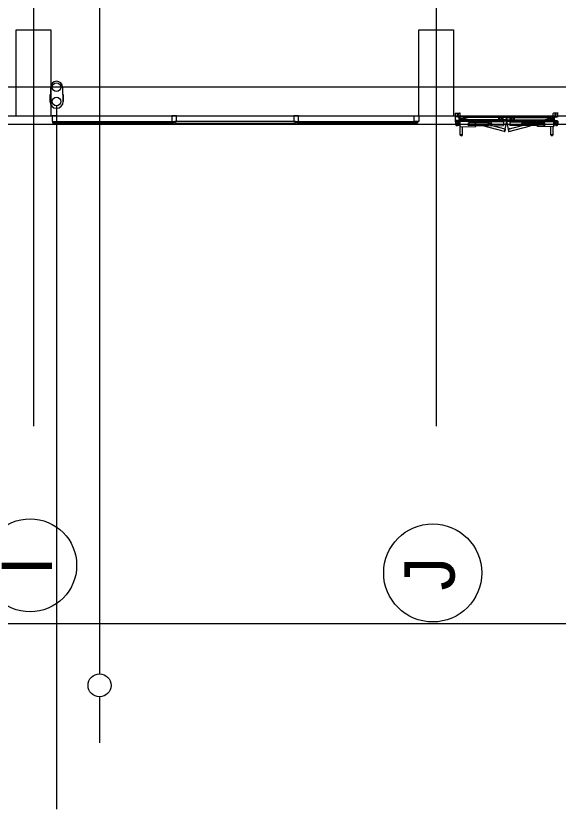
# Model space of a CAD drawing. Extents: x -264205 to -263659, y -1242401 to -1242060.
# Drawn here: x -263862.78 to -263853.35, y -1242253.37 to -1242239.57 of the extents above; entities that cross this region are included whole.
import ezdxf

# ---------------------------------------------------------------- set-up
doc = ezdxf.new("R2010")
doc.units = 0
for name, color, linetype in [('OBRUBNIKY_KOMUNIKACIE_PROJEKT', 7, 'Continuous'), ('OSI_STAVBY_KFA', 7, 'Continuous'), ('SITUACIA_DSP_2D', 7, 'Continuous')]:
    doc.layers.add(name, color=color, linetype=linetype)

msp = doc.modelspace()

# ---------------------------------------------------------------- linework, layer by layer
at = {"layer": 'OBRUBNIKY_KOMUNIKACIE_PROJEKT'}
msp.add_line((-263822.79, -1242241.457), (-263894.968, -1242241.457), dxfattribs=at)
at = {"layer": 'OSI_STAVBY_KFA'}
for p, q in [((-263862.468, -1242083.237), (-263862.468, -1242246.707)), ((-263855.468, -1242083.237), (-263855.468, -1242246.707)), ((-263792.653, -1242240.807), (-263911.523, -1242240.807))]:
    msp.add_line(p, q, dxfattribs=at)
for centre, radius in [((-263862.528, -1242249.126), 0.809), ((-263855.528, -1242249.258), 0.853)]:
    msp.add_circle(centre, radius, dxfattribs=at)
at = {"layer": 'SITUACIA_DSP_2D'}
for p, q in [((-263861.318, -1242235.757), (-263861.321, -1242251.015)), ((-263862.768, -1242241.312), (-263862.768, -1242239.812)), ((-263862.768, -1242239.812), (-263862.168, -1242239.812)), ((-263862.168, -1242239.812), (-263862.168, -1242241.312)), ((-263855.768, -1242241.312), (-263855.768, -1242239.812)), ((-263855.768, -1242239.812), (-263855.168, -1242239.812)), ((-263855.168, -1242239.812), (-263855.168, -1242241.312)), ((-263862.171, -1242240.807), (-263862.171, -1242240.932)), ((-263861.965, -1242240.807), (-263861.965, -1242240.932)), ((-263862.171, -1242240.932), (-263862.185, -1242240.946)), ((-263862.185, -1242240.946), (-263862.185, -1242241.057)), ((-263861.965, -1242240.932), (-263861.951, -1242240.946)), ((-263861.951, -1242240.946), (-263861.951, -1242241.057)), ((-263861.951, -1242241.057), (-263861.951, -1242240.946)), ((-263862.068, -1242241.132), (-263862.068, -1242253.368)), ((-263894.581, -1242241.307), (-263822.79, -1242241.307)), ((-263862.168, -1242241.312), (-263862.768, -1242241.312)), ((-263862.063, -1242241.307), (-263862.143, -1242241.307)), ((-263862.143, -1242241.307), (-263862.143, -1242241.407)), ((-263862.063, -1242241.407), (-263862.063, -1242241.307)), ((-263859.983, -1242241.307), (-263860.063, -1242241.307)), ((-263860.063, -1242241.307), (-263860.063, -1242241.407)), ((-263859.983, -1242241.407), (-263859.983, -1242241.307)), ((-263857.863, -1242241.307), (-263857.943, -1242241.307)), ((-263857.943, -1242241.307), (-263857.943, -1242241.407)), ((-263857.863, -1242241.407), (-263857.863, -1242241.307)), ((-263855.848, -1242241.407), (-263855.848, -1242241.307)), ((-263855.848, -1242241.307), (-263855.768, -1242241.307)), ((-263855.768, -1242241.307), (-263855.768, -1242241.407)), ((-263855.168, -1242241.312), (-263855.768, -1242241.312)), ((-263855.137, -1242241.257), (-263855.061, -1242241.257)), ((-263855.137, -1242241.307), (-263855.137, -1242241.407)), ((-263854.243, -1242241.317), (-263855.137, -1242241.317)), ((-263855.131, -1242241.317), (-263855.131, -1242241.257)), ((-263855.121, -1242241.325), (-263855.121, -1242241.317)), ((-263855.1, -1242241.325), (-263855.121, -1242241.325)), ((-263855.104, -1242241.282), (-263855.078, -1242241.282)), ((-263855.091, -1242241.295), (-263855.091, -1242241.269)), ((-263855.057, -1242241.397), (-263855.057, -1242241.317)), ((-263855.051, -1242241.317), (-263855.051, -1242241.267)), ((-263855.051, -1242241.397), (-263855.051, -1242241.317)), ((-263854.248, -1242241.337), (-263855.006, -1242241.337)), ((-263855.006, -1242241.377), (-263855.006, -1242241.337)), ((-263854.25, -1242241.335), (-263854.28, -1242241.335)), ((-263854.28, -1242241.337), (-263854.28, -1242241.335)), ((-263854.248, -1242241.377), (-263854.248, -1242241.337)), ((-263854.246, -1242241.375), (-263854.246, -1242241.339)), ((-263854.243, -1242241.317), (-263853.348, -1242241.317)), ((-263854.24, -1242241.375), (-263854.24, -1242241.339)), ((-263854.238, -1242241.337), (-263853.479, -1242241.337)), ((-263854.238, -1242241.377), (-263854.238, -1242241.337)), ((-263854.236, -1242241.335), (-263854.206, -1242241.335)), ((-263854.206, -1242241.337), (-263854.206, -1242241.335)), ((-263853.479, -1242241.377), (-263853.479, -1242241.337)), ((-263853.434, -1242241.317), (-263853.434, -1242241.267)), ((-263853.434, -1242241.397), (-263853.434, -1242241.317)), ((-263853.428, -1242241.397), (-263853.428, -1242241.317)), ((-263853.348, -1242241.257), (-263853.424, -1242241.257)), ((-263853.381, -1242241.282), (-263853.407, -1242241.282)), ((-263853.394, -1242241.295), (-263853.394, -1242241.269)), ((-263853.385, -1242241.325), (-263853.364, -1242241.325)), ((-263853.364, -1242241.325), (-263853.364, -1242241.317)), ((-263853.354, -1242241.317), (-263853.354, -1242241.257)), ((-263822.79, -1242241.457), (-263894.968, -1242241.457)), ((-263862.143, -1242241.407), (-263862.103, -1242241.407)), ((-263862.133, -1242241.432), (-263862.133, -1242241.407)), ((-263862.133, -1242241.407), (-263860.033, -1242241.407)), ((-263860.033, -1242241.432), (-263862.133, -1242241.432)), ((-263862.103, -1242241.407), (-263862.063, -1242241.407)), ((-263860.063, -1242241.407), (-263860.023, -1242241.407)), ((-263860.033, -1242241.407), (-263860.033, -1242241.432)), ((-263860.023, -1242241.407), (-263859.983, -1242241.407)), ((-263857.913, -1242241.407), (-263860.013, -1242241.407)), ((-263860.013, -1242241.407), (-263860.013, -1242241.432)), ((-263860.013, -1242241.432), (-263857.913, -1242241.432)), ((-263857.943, -1242241.407), (-263857.853, -1242241.407)), ((-263857.913, -1242241.432), (-263857.913, -1242241.407)), ((-263857.893, -1242241.432), (-263857.893, -1242241.407)), ((-263857.893, -1242241.407), (-263855.793, -1242241.407)), ((-263855.793, -1242241.432), (-263857.893, -1242241.432)), ((-263857.853, -1242241.407), (-263857.863, -1242241.407)), ((-263855.808, -1242241.407), (-263855.848, -1242241.407)), ((-263855.768, -1242241.407), (-263855.808, -1242241.407)), ((-263855.793, -1242241.407), (-263855.793, -1242241.432)), ((-263854.243, -1242241.397), (-263855.137, -1242241.397)), ((-263855.132, -1242241.397), (-263855.132, -1242241.407)), ((-263855.132, -1242241.397), (-263855.062, -1242241.397)), ((-263855.132, -1242241.407), (-263855.132, -1242241.457)), ((-263855.132, -1242241.407), (-263855.062, -1242241.407)), ((-263855.113, -1242241.407), (-263855.13, -1242241.407)), ((-263855.13, -1242241.409), (-263855.13, -1242241.407)), ((-263855.113, -1242241.409), (-263855.13, -1242241.409)), ((-263855.115, -1242241.409), (-263855.128, -1242241.409)), ((-263855.128, -1242241.409), (-263855.128, -1242241.415)), ((-263855.128, -1242241.415), (-263855.115, -1242241.415)), ((-263855.127, -1242241.457), (-263855.096, -1242241.457)), ((-263855.122, -1242241.417), (-263855.122, -1242241.403)), ((-263855.122, -1242241.409), (-263855.122, -1242241.414)), ((-263855.122, -1242241.451), (-263855.112, -1242241.445)), ((-263855.122, -1242241.463), (-263855.122, -1242241.451)), ((-263855.112, -1242241.469), (-263855.122, -1242241.463)), ((-263855.1, -1242241.39), (-263855.121, -1242241.39)), ((-263855.121, -1242241.397), (-263855.121, -1242241.39)), ((-263855.115, -1242241.415), (-263855.115, -1242241.409)), ((-263855.113, -1242241.409), (-263855.113, -1242241.407)), ((-263855.056, -1242241.441), (-263855.112, -1242241.442)), ((-263855.112, -1242241.473), (-263855.112, -1242241.442)), ((-263855.112, -1242241.445), (-263855.101, -1242241.451)), ((-263855.101, -1242241.463), (-263855.112, -1242241.469)), ((-263855.111, -1242241.472), (-263855.055, -1242241.471)), ((-263855.101, -1242241.451), (-263855.101, -1242241.463)), ((-263855.092, -1242241.407), (-263855.092, -1242241.442)), ((-263855.092, -1242241.432), (-263855.081, -1242241.432)), ((-263855.091, -1242241.442), (-263855.091, -1242241.423)), ((-263855.064, -1242241.407), (-263855.081, -1242241.407)), ((-263855.081, -1242241.409), (-263855.081, -1242241.407)), ((-263855.064, -1242241.409), (-263855.081, -1242241.409)), ((-263855.066, -1242241.409), (-263855.079, -1242241.409)), ((-263855.079, -1242241.409), (-263855.079, -1242241.415)), ((-263855.079, -1242241.415), (-263855.066, -1242241.415)), ((-263855.073, -1242241.417), (-263855.073, -1242241.403)), ((-263855.073, -1242241.409), (-263855.073, -1242241.414)), ((-263855.066, -1242241.415), (-263855.066, -1242241.409)), ((-263855.064, -1242241.409), (-263855.064, -1242241.407)), ((-263855.062, -1242241.397), (-263855.062, -1242241.407)), ((-263855.057, -1242241.345), (-263855.057, -1242241.37)), ((-263855.057, -1242241.345), (-263855.047, -1242241.345)), ((-263855.057, -1242241.37), (-263855.047, -1242241.37)), ((-263854.781, -1242241.407), (-263855.056, -1242241.413)), ((-263855.056, -1242241.413), (-263855.055, -1242241.5)), ((-263855.012, -1242241.383), (-263855.052, -1242241.383)), ((-263855.052, -1242241.413), (-263855.052, -1242241.383)), ((-263855.051, -1242241.413), (-263855.051, -1242241.397)), ((-263855.047, -1242241.345), (-263855.047, -1242241.37)), ((-263855.047, -1242241.356), (-263855.037, -1242241.349)), ((-263855.047, -1242241.358), (-263855.047, -1242241.356)), ((-263855.037, -1242241.365), (-263855.047, -1242241.358)), ((-263855.044, -1242241.373), (-263855.019, -1242241.373)), ((-263855.044, -1242241.383), (-263855.044, -1242241.373)), ((-263855.044, -1242241.383), (-263855.019, -1242241.383)), ((-263855.04, -1242241.363), (-263855.033, -1242241.373)), ((-263855.033, -1242241.373), (-263855.031, -1242241.373)), ((-263855.031, -1242241.373), (-263855.023, -1242241.363)), ((-263855.028, -1242241.367), (-263855.017, -1242241.362)), ((-263855.026, -1242241.349), (-263855.016, -1242241.356)), ((-263855.016, -1242241.358), (-263855.026, -1242241.365)), ((-263855.016, -1242241.36), (-263855.024, -1242241.351)), ((-263855.02, -1242241.373), (-263855.013, -1242241.349)), ((-263855.01, -1242241.376), (-263855.02, -1242241.373)), ((-263855.019, -1242241.383), (-263855.019, -1242241.373)), ((-263855.017, -1242241.362), (-263855.016, -1242241.36)), ((-263855.006, -1242241.345), (-263855.016, -1242241.345)), ((-263855.016, -1242241.345), (-263855.016, -1242241.37)), ((-263855.016, -1242241.356), (-263855.016, -1242241.358)), ((-263855.006, -1242241.37), (-263855.016, -1242241.37)), ((-263855.004, -1242241.352), (-263855.013, -1242241.349)), ((-263855.002, -1242241.345), (-263855.012, -1242241.383)), ((-263855.012, -1242241.412), (-263855.012, -1242241.383)), ((-263854.96, -1242241.397), (-263855.012, -1242241.383)), ((-263855.006, -1242241.345), (-263855.006, -1242241.37)), ((-263854.248, -1242241.377), (-263855.006, -1242241.377)), ((-263854.805, -1242241.397), (-263855.002, -1242241.345)), ((-263854.781, -1242241.426), (-263854.907, -1242241.428)), ((-263854.906, -1242241.478), (-263854.907, -1242241.428)), ((-263854.78, -1242241.476), (-263854.906, -1242241.478)), ((-263854.896, -1242241.478), (-263854.897, -1242241.428)), ((-263854.79, -1242241.476), (-263854.791, -1242241.426)), ((-263854.78, -1242241.494), (-263854.781, -1242241.407)), ((-263854.3, -1242241.411), (-263854.781, -1242241.42)), ((-263854.558, -1242241.426), (-263854.781, -1242241.431)), ((-263854.557, -1242241.466), (-263854.78, -1242241.471)), ((-263854.78, -1242241.481), (-263854.299, -1242241.472)), ((-263854.279, -1242241.578), (-263854.656, -1242241.479)), ((-263854.557, -1242241.466), (-263854.558, -1242241.426)), ((-263854.553, -1242241.436), (-263854.558, -1242241.436)), ((-263854.553, -1242241.456), (-263854.558, -1242241.456)), ((-263854.553, -1242241.456), (-263854.553, -1242241.436)), ((-263854.553, -1242241.438), (-263854.552, -1242241.436)), ((-263854.553, -1242241.455), (-263854.553, -1242241.438)), ((-263854.553, -1242241.455), (-263854.552, -1242241.456)), ((-263854.546, -1242241.436), (-263854.552, -1242241.436)), ((-263854.546, -1242241.441), (-263854.552, -1242241.441)), ((-263854.545, -1242241.451), (-263854.552, -1242241.451)), ((-263854.545, -1242241.456), (-263854.552, -1242241.456)), ((-263854.545, -1242241.437), (-263854.546, -1242241.436)), ((-263854.545, -1242241.454), (-263854.545, -1242241.437)), ((-263854.537, -1242241.441), (-263854.545, -1242241.441)), ((-263854.537, -1242241.451), (-263854.545, -1242241.451)), ((-263854.545, -1242241.454), (-263854.545, -1242241.456)), ((-263854.537, -1242241.441), (-263854.524, -1242241.433)), ((-263854.537, -1242241.441), (-263854.537, -1242241.451)), ((-263854.537, -1242241.451), (-263854.523, -1242241.458)), ((-263854.269, -1242241.539), (-263854.512, -1242241.476)), ((-263854.305, -1242241.343), (-263854.38, -1242241.343)), ((-263854.38, -1242241.397), (-263854.38, -1242241.343)), ((-263854.38, -1242241.403), (-263854.38, -1242241.397)), ((-263854.305, -1242241.403), (-263854.38, -1242241.403)), ((-263854.369, -1242241.35), (-263854.373, -1242241.357)), ((-263854.373, -1242241.357), (-263854.369, -1242241.364)), ((-263854.361, -1242241.35), (-263854.369, -1242241.35)), ((-263854.369, -1242241.364), (-263854.361, -1242241.364)), ((-263854.357, -1242241.357), (-263854.361, -1242241.35)), ((-263854.361, -1242241.364), (-263854.357, -1242241.357)), ((-263854.324, -1242241.35), (-263854.328, -1242241.357)), ((-263854.328, -1242241.357), (-263854.324, -1242241.364)), ((-263854.316, -1242241.35), (-263854.324, -1242241.35)), ((-263854.324, -1242241.364), (-263854.316, -1242241.364)), ((-263854.312, -1242241.357), (-263854.316, -1242241.35)), ((-263854.316, -1242241.364), (-263854.312, -1242241.357)), ((-263854.305, -1242241.397), (-263854.305, -1242241.343)), ((-263854.305, -1242241.403), (-263854.305, -1242241.397)), ((-263854.3, -1242241.411), (-263854.299, -1242241.472)), ((-263854.28, -1242241.379), (-263854.28, -1242241.377)), ((-263854.25, -1242241.379), (-263854.28, -1242241.379)), ((-263854.265, -1242241.38), (-263854.265, -1242241.377)), ((-263854.249, -1242241.374), (-263854.249, -1242241.383)), ((-263854.243, -1242241.397), (-263853.348, -1242241.397)), ((-263854.238, -1242241.377), (-263853.479, -1242241.377)), ((-263854.236, -1242241.374), (-263854.236, -1242241.383)), ((-263854.236, -1242241.379), (-263854.206, -1242241.379)), ((-263854.22, -1242241.38), (-263854.22, -1242241.377)), ((-263854.216, -1242241.539), (-263853.973, -1242241.476)), ((-263854.206, -1242241.379), (-263854.206, -1242241.377)), ((-263854.206, -1242241.578), (-263853.829, -1242241.479)), ((-263854.185, -1242241.411), (-263854.186, -1242241.472)), ((-263853.705, -1242241.481), (-263854.186, -1242241.472)), ((-263854.185, -1242241.411), (-263853.704, -1242241.42)), ((-263854.18, -1242241.343), (-263854.105, -1242241.343)), ((-263854.18, -1242241.397), (-263854.18, -1242241.343)), ((-263854.18, -1242241.403), (-263854.18, -1242241.397)), ((-263854.18, -1242241.403), (-263854.105, -1242241.403)), ((-263854.173, -1242241.357), (-263854.169, -1242241.35)), ((-263854.169, -1242241.364), (-263854.173, -1242241.357)), ((-263854.169, -1242241.35), (-263854.161, -1242241.35)), ((-263854.161, -1242241.364), (-263854.169, -1242241.364)), ((-263854.161, -1242241.35), (-263854.157, -1242241.357)), ((-263854.157, -1242241.357), (-263854.161, -1242241.364)), ((-263854.128, -1242241.357), (-263854.124, -1242241.35)), ((-263854.124, -1242241.364), (-263854.128, -1242241.357)), ((-263854.124, -1242241.35), (-263854.116, -1242241.35)), ((-263854.116, -1242241.364), (-263854.124, -1242241.364)), ((-263854.116, -1242241.35), (-263854.112, -1242241.357)), ((-263854.112, -1242241.357), (-263854.116, -1242241.364)), ((-263854.105, -1242241.397), (-263854.105, -1242241.343)), ((-263854.105, -1242241.403), (-263854.105, -1242241.397)), ((-263853.948, -1242241.451), (-263853.962, -1242241.458)), ((-263853.948, -1242241.441), (-263853.961, -1242241.433)), ((-263853.948, -1242241.441), (-263853.948, -1242241.451)), ((-263853.948, -1242241.441), (-263853.94, -1242241.441)), ((-263853.948, -1242241.451), (-263853.94, -1242241.451)), ((-263853.94, -1242241.437), (-263853.939, -1242241.436)), ((-263853.94, -1242241.454), (-263853.94, -1242241.437)), ((-263853.94, -1242241.451), (-263853.933, -1242241.451)), ((-263853.94, -1242241.454), (-263853.94, -1242241.456)), ((-263853.94, -1242241.456), (-263853.933, -1242241.456)), ((-263853.939, -1242241.436), (-263853.933, -1242241.436)), ((-263853.939, -1242241.441), (-263853.933, -1242241.441)), ((-263853.932, -1242241.438), (-263853.933, -1242241.436)), ((-263853.932, -1242241.455), (-263853.933, -1242241.456)), ((-263853.932, -1242241.436), (-263853.927, -1242241.436)), ((-263853.932, -1242241.456), (-263853.932, -1242241.436)), ((-263853.932, -1242241.455), (-263853.932, -1242241.438)), ((-263853.932, -1242241.456), (-263853.927, -1242241.456)), ((-263853.928, -1242241.466), (-263853.927, -1242241.426)), ((-263853.928, -1242241.466), (-263853.705, -1242241.471)), ((-263853.927, -1242241.426), (-263853.704, -1242241.431)), ((-263853.705, -1242241.494), (-263853.704, -1242241.407)), ((-263853.705, -1242241.476), (-263853.579, -1242241.478)), ((-263853.704, -1242241.407), (-263853.429, -1242241.413)), ((-263853.704, -1242241.426), (-263853.578, -1242241.428)), ((-263853.695, -1242241.476), (-263853.694, -1242241.426)), ((-263853.68, -1242241.397), (-263853.483, -1242241.345)), ((-263853.589, -1242241.478), (-263853.588, -1242241.428)), ((-263853.579, -1242241.478), (-263853.578, -1242241.428)), ((-263853.526, -1242241.397), (-263853.473, -1242241.383)), ((-263853.483, -1242241.345), (-263853.473, -1242241.383)), ((-263853.481, -1242241.352), (-263853.472, -1242241.349)), ((-263853.479, -1242241.345), (-263853.469, -1242241.345)), ((-263853.479, -1242241.345), (-263853.479, -1242241.37)), ((-263853.479, -1242241.37), (-263853.469, -1242241.37)), ((-263853.475, -1242241.376), (-263853.465, -1242241.373)), ((-263853.474, -1242241.383), (-263853.434, -1242241.383)), ((-263853.474, -1242241.412), (-263853.474, -1242241.383)), ((-263853.465, -1242241.373), (-263853.472, -1242241.349)), ((-263853.469, -1242241.345), (-263853.469, -1242241.37)), ((-263853.459, -1242241.349), (-263853.469, -1242241.356)), ((-263853.469, -1242241.36), (-263853.461, -1242241.351)), ((-263853.469, -1242241.356), (-263853.469, -1242241.358)), ((-263853.469, -1242241.358), (-263853.459, -1242241.365)), ((-263853.468, -1242241.362), (-263853.469, -1242241.36)), ((-263853.457, -1242241.367), (-263853.468, -1242241.362)), ((-263853.441, -1242241.373), (-263853.466, -1242241.373)), ((-263853.466, -1242241.383), (-263853.466, -1242241.373)), ((-263853.441, -1242241.383), (-263853.466, -1242241.383)), ((-263853.455, -1242241.373), (-263853.462, -1242241.363)), ((-263853.453, -1242241.373), (-263853.455, -1242241.373)), ((-263853.445, -1242241.363), (-263853.453, -1242241.373)), ((-263853.438, -1242241.356), (-263853.448, -1242241.349)), ((-263853.448, -1242241.365), (-263853.438, -1242241.358)), ((-263853.441, -1242241.383), (-263853.441, -1242241.373)), ((-263853.438, -1242241.345), (-263853.438, -1242241.37)), ((-263853.428, -1242241.345), (-263853.438, -1242241.345)), ((-263853.438, -1242241.358), (-263853.438, -1242241.356)), ((-263853.428, -1242241.37), (-263853.438, -1242241.37)), ((-263853.434, -1242241.413), (-263853.434, -1242241.383)), ((-263853.434, -1242241.413), (-263853.434, -1242241.397)), ((-263853.429, -1242241.413), (-263853.43, -1242241.5)), ((-263853.374, -1242241.472), (-263853.43, -1242241.471)), ((-263853.429, -1242241.441), (-263853.373, -1242241.442)), ((-263853.428, -1242241.345), (-263853.428, -1242241.37)), ((-263853.423, -1242241.397), (-263853.423, -1242241.407)), ((-263853.353, -1242241.397), (-263853.423, -1242241.397)), ((-263853.353, -1242241.407), (-263853.423, -1242241.407)), ((-263853.421, -1242241.407), (-263853.404, -1242241.407)), ((-263853.421, -1242241.409), (-263853.421, -1242241.407)), ((-263853.421, -1242241.409), (-263853.404, -1242241.409)), ((-263853.419, -1242241.409), (-263853.406, -1242241.409)), ((-263853.419, -1242241.415), (-263853.419, -1242241.409)), ((-263853.406, -1242241.415), (-263853.419, -1242241.415)), ((-263853.413, -1242241.417), (-263853.413, -1242241.403)), ((-263853.413, -1242241.409), (-263853.413, -1242241.414)), ((-263853.406, -1242241.409), (-263853.406, -1242241.415)), ((-263853.404, -1242241.409), (-263853.404, -1242241.407)), ((-263853.394, -1242241.432), (-263853.404, -1242241.432)), ((-263853.394, -1242241.407), (-263853.394, -1242241.442)), ((-263853.394, -1242241.442), (-263853.394, -1242241.423)), ((-263853.358, -1242241.457), (-263853.389, -1242241.457)), ((-263853.385, -1242241.39), (-263853.364, -1242241.39)), ((-263853.374, -1242241.445), (-263853.384, -1242241.451)), ((-263853.384, -1242241.451), (-263853.384, -1242241.463)), ((-263853.384, -1242241.463), (-263853.374, -1242241.469)), ((-263853.374, -1242241.473), (-263853.374, -1242241.442)), ((-263853.363, -1242241.451), (-263853.374, -1242241.445)), ((-263853.374, -1242241.469), (-263853.363, -1242241.463)), ((-263853.372, -1242241.407), (-263853.355, -1242241.407)), ((-263853.372, -1242241.409), (-263853.372, -1242241.407)), ((-263853.372, -1242241.409), (-263853.355, -1242241.409)), ((-263853.37, -1242241.409), (-263853.357, -1242241.409)), ((-263853.37, -1242241.415), (-263853.37, -1242241.409)), ((-263853.357, -1242241.415), (-263853.37, -1242241.415)), ((-263853.364, -1242241.397), (-263853.364, -1242241.39)), ((-263853.364, -1242241.417), (-263853.364, -1242241.403)), ((-263853.364, -1242241.409), (-263853.364, -1242241.414)), ((-263853.363, -1242241.463), (-263853.363, -1242241.451)), ((-263853.357, -1242241.409), (-263853.357, -1242241.415)), ((-263853.355, -1242241.409), (-263853.355, -1242241.407)), ((-263853.354, -1242241.407), (-263853.354, -1242241.457)), ((-263853.353, -1242241.397), (-263853.353, -1242241.407)), ((-263855.055, -1242241.5), (-263854.78, -1242241.494)), ((-263855.052, -1242241.643), (-263855.052, -1242241.5)), ((-263855.012, -1242241.643), (-263855.012, -1242241.499)), ((-263854.31, -1242241.571), (-263854.31, -1242241.569)), ((-263854.281, -1242241.579), (-263854.31, -1242241.571)), ((-263854.3, -1242241.531), (-263854.299, -1242241.529)), ((-263854.299, -1242241.529), (-263854.27, -1242241.536)), ((-263854.269, -1242241.539), (-263854.279, -1242241.578)), ((-263854.267, -1242241.541), (-263854.277, -1242241.576)), ((-263854.218, -1242241.541), (-263854.209, -1242241.576)), ((-263854.216, -1242241.539), (-263854.206, -1242241.578)), ((-263854.186, -1242241.529), (-263854.215, -1242241.536)), ((-263854.204, -1242241.579), (-263854.175, -1242241.571)), ((-263854.185, -1242241.531), (-263854.186, -1242241.529)), ((-263854.175, -1242241.571), (-263854.175, -1242241.569)), ((-263853.43, -1242241.5), (-263853.705, -1242241.494)), ((-263853.474, -1242241.643), (-263853.474, -1242241.499)), ((-263853.434, -1242241.643), (-263853.434, -1242241.5)), ((-263855.052, -1242241.643), (-263855.04, -1242241.643)), ((-263855.04, -1242241.643), (-263855.036, -1242241.628)), ((-263855.036, -1242241.628), (-263855.027, -1242241.658)), ((-263855.027, -1242241.658), (-263855.023, -1242241.643)), ((-263855.023, -1242241.643), (-263855.012, -1242241.643)), ((-263853.462, -1242241.643), (-263853.474, -1242241.643)), ((-263853.458, -1242241.658), (-263853.462, -1242241.643)), ((-263853.449, -1242241.628), (-263853.458, -1242241.658)), ((-263853.445, -1242241.643), (-263853.449, -1242241.628)), ((-263853.434, -1242241.643), (-263853.445, -1242241.643)), ((-263924.143, -1242250.14), (-263822.79, -1242250.14)), ((-263861.321, -1242251.415), (-263861.321, -1242252.215))]:
    msp.add_line(p, q, dxfattribs=at)
for centre, radius in [((-263862.068, -1242240.807), 0.075), ((-263862.068, -1242241.057), 0.075), ((-263855.091, -1242241.282), 0.008), ((-263853.394, -1242241.282), 0.008), ((-263855.112, -1242241.457), 0.0126), ((-263855.112, -1242241.457), 0.0102), ((-263854.517, -1242241.445), 0.00952), ((-263854.517, -1242241.445), 0.00645), ((-263854.517, -1242241.445), 0.005), ((-263854.365, -1242241.357), 0.0084), ((-263854.365, -1242241.357), 0.0068), ((-263854.32, -1242241.357), 0.0084), ((-263854.32, -1242241.357), 0.0068), ((-263854.165, -1242241.357), 0.0084), ((-263854.165, -1242241.357), 0.0068), ((-263854.12, -1242241.357), 0.0084), ((-263854.12, -1242241.357), 0.0068), ((-263853.968, -1242241.445), 0.00952), ((-263853.968, -1242241.445), 0.00645), ((-263853.968, -1242241.445), 0.005), ((-263853.374, -1242241.457), 0.0126), ((-263853.374, -1242241.457), 0.0102), ((-263861.321, -1242251.215), 0.2)]:
    msp.add_circle(centre, radius, dxfattribs=at)
for centre, radius, start, end in [((-263862.068, -1242240.807), 0.103, 360, 180), ((-263862.068, -1242241.057), 0.117, 180, 360), ((-263855.1, -1242241.357), 0.0325, 270, 90), ((-263855.061, -1242241.267), 0.01, 0, 90), ((-263854.25, -1242241.339), 0.004, 0, 90), ((-263854.236, -1242241.339), 0.004, 90, 180), ((-263853.424, -1242241.267), 0.01, 90, 180), ((-263853.385, -1242241.357), 0.0325, 90, 270), ((-263855.112, -1242241.457), 0.02, 180, 312.5496), ((-263855.125, -1242241.408), 0.0068, 240, 300), ((-263855.112, -1242241.457), 0.015, 91.14, 271.14), ((-263855.118, -1242241.408), 0.0068, 240, 300), ((-263855.091, -1242241.432), 0.008, 266.4167, 93.5833), ((-263855.076, -1242241.408), 0.0068, 240, 300), ((-263855.069, -1242241.408), 0.0068, 240, 300), ((-263855.032, -1242241.357), 0.01, 53.6139, 306.3861), ((-263855.032, -1242241.357), 0.01, 323.6139, 216.3861), ((-263855.032, -1242241.357), 0.01, 38.6139, 291.3861), ((-263855.032, -1242241.357), 0.01, 233.6139, 126.3861), ((-263854.549, -1242241.439), 0.00432, 146.5466, 215.7334), ((-263854.537, -1242241.446), 0.0161, 163.4401, 198.8399), ((-263854.548, -1242241.453), 0.00432, 146.5466, 215.7334), ((-263854.552, -1242241.451), 0.0001, 21.9532, 91.14), ((-263854.549, -1242241.439), 0.00432, 326.5466, 35.7334), ((-263854.561, -1242241.446), 0.0161, 343.4401, 18.8399), ((-263854.545, -1242241.451), 0.0001, 91.14, 160.3268), ((-263854.549, -1242241.453), 0.00432, 326.5466, 35.7334), ((-263854.517, -1242241.445), 0.014, 242.4029, 119.8771), ((-263855.032, -1242241.357), 0.786, 345, 0), ((-263854.25, -1242241.375), 0.004, 270, 0), ((-263853.454, -1242241.357), 0.786, 180, 195), ((-263854.236, -1242241.375), 0.004, 180, 270), ((-263853.968, -1242241.445), 0.014, 60.1229, 297.5971), ((-263853.936, -1242241.439), 0.00432, 144.2666, 213.4534), ((-263853.924, -1242241.446), 0.0161, 161.1601, 196.5599), ((-263853.936, -1242241.453), 0.00432, 144.2666, 213.4534), ((-263853.94, -1242241.451), 0.0001, 19.6732, 88.86), ((-263853.936, -1242241.439), 0.00432, 324.2666, 33.4534), ((-263853.948, -1242241.446), 0.0161, 341.1601, 16.5599), ((-263853.937, -1242241.453), 0.00432, 324.2666, 33.4534), ((-263853.933, -1242241.451), 0.0001, 88.86, 158.0468), ((-263853.454, -1242241.357), 0.01, 53.6139, 306.3861), ((-263853.454, -1242241.357), 0.01, 323.6139, 216.3861), ((-263853.454, -1242241.357), 0.01, 248.6139, 141.3861), ((-263853.454, -1242241.357), 0.01, 233.6139, 126.3861), ((-263853.416, -1242241.408), 0.0068, 240, 300), ((-263853.409, -1242241.408), 0.0068, 240, 300), ((-263853.394, -1242241.432), 0.008, 86.4167, 273.5833), ((-263853.374, -1242241.457), 0.02, 227.4504, 0), ((-263853.374, -1242241.457), 0.015, 268.86, 88.86), ((-263853.367, -1242241.408), 0.0068, 240, 300), ((-263853.36, -1242241.408), 0.0068, 240, 300), ((-263854.28, -1242241.575), 0.004, 255, 345), ((-263854.271, -1242241.54), 0.004, 345, 75), ((-263854.214, -1242241.54), 0.004, 105, 195), ((-263854.205, -1242241.575), 0.004, 195, 285)]:
    msp.add_arc(centre, radius, start, end, dxfattribs=at)

# ---------------------------------------------------------------- texts
at = {"layer": 'OSI_STAVBY_KFA'}
for s, p in [('J', (-263855.147, -1242249.564)), ('I', (-263862.147, -1242249.296))]:
    msp.add_text(s, height=0.875, rotation=90, dxfattribs=at).set_placement(p)

doc.saveas('drawing.dxf')
